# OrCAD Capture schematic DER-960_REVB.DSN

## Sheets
1 PAGE1: size Custom; title: HIPERPFS5 -220W Design
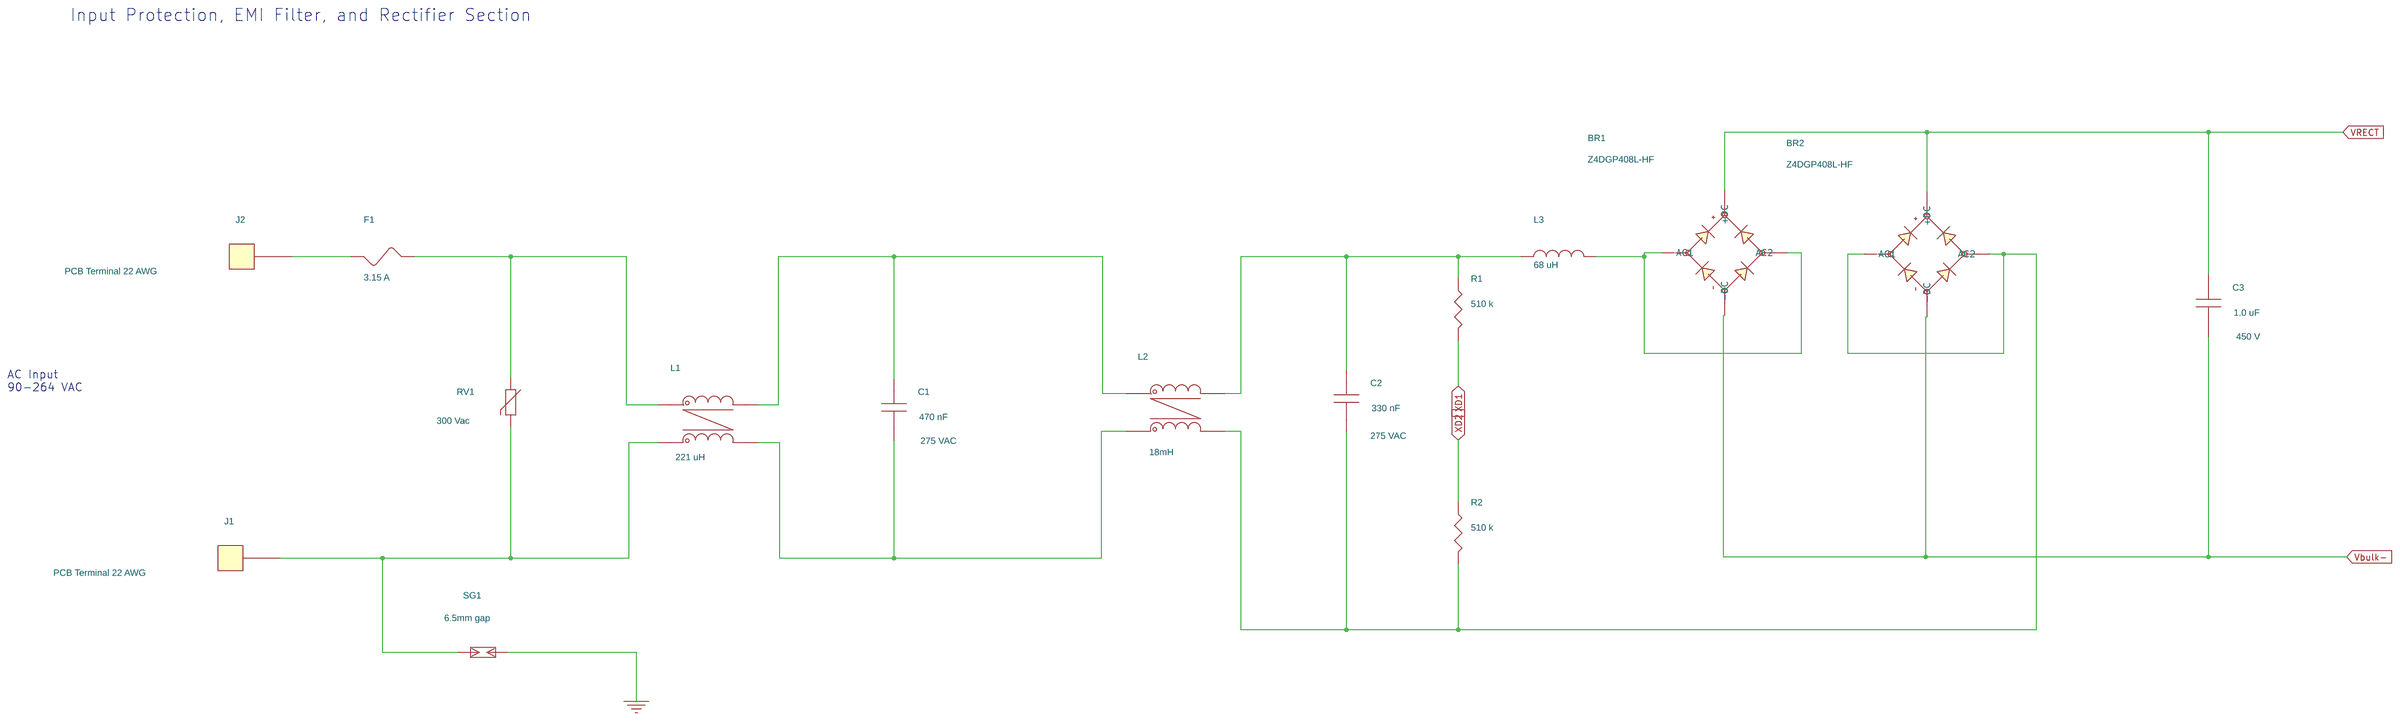
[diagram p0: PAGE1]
2 PAGE2: size C
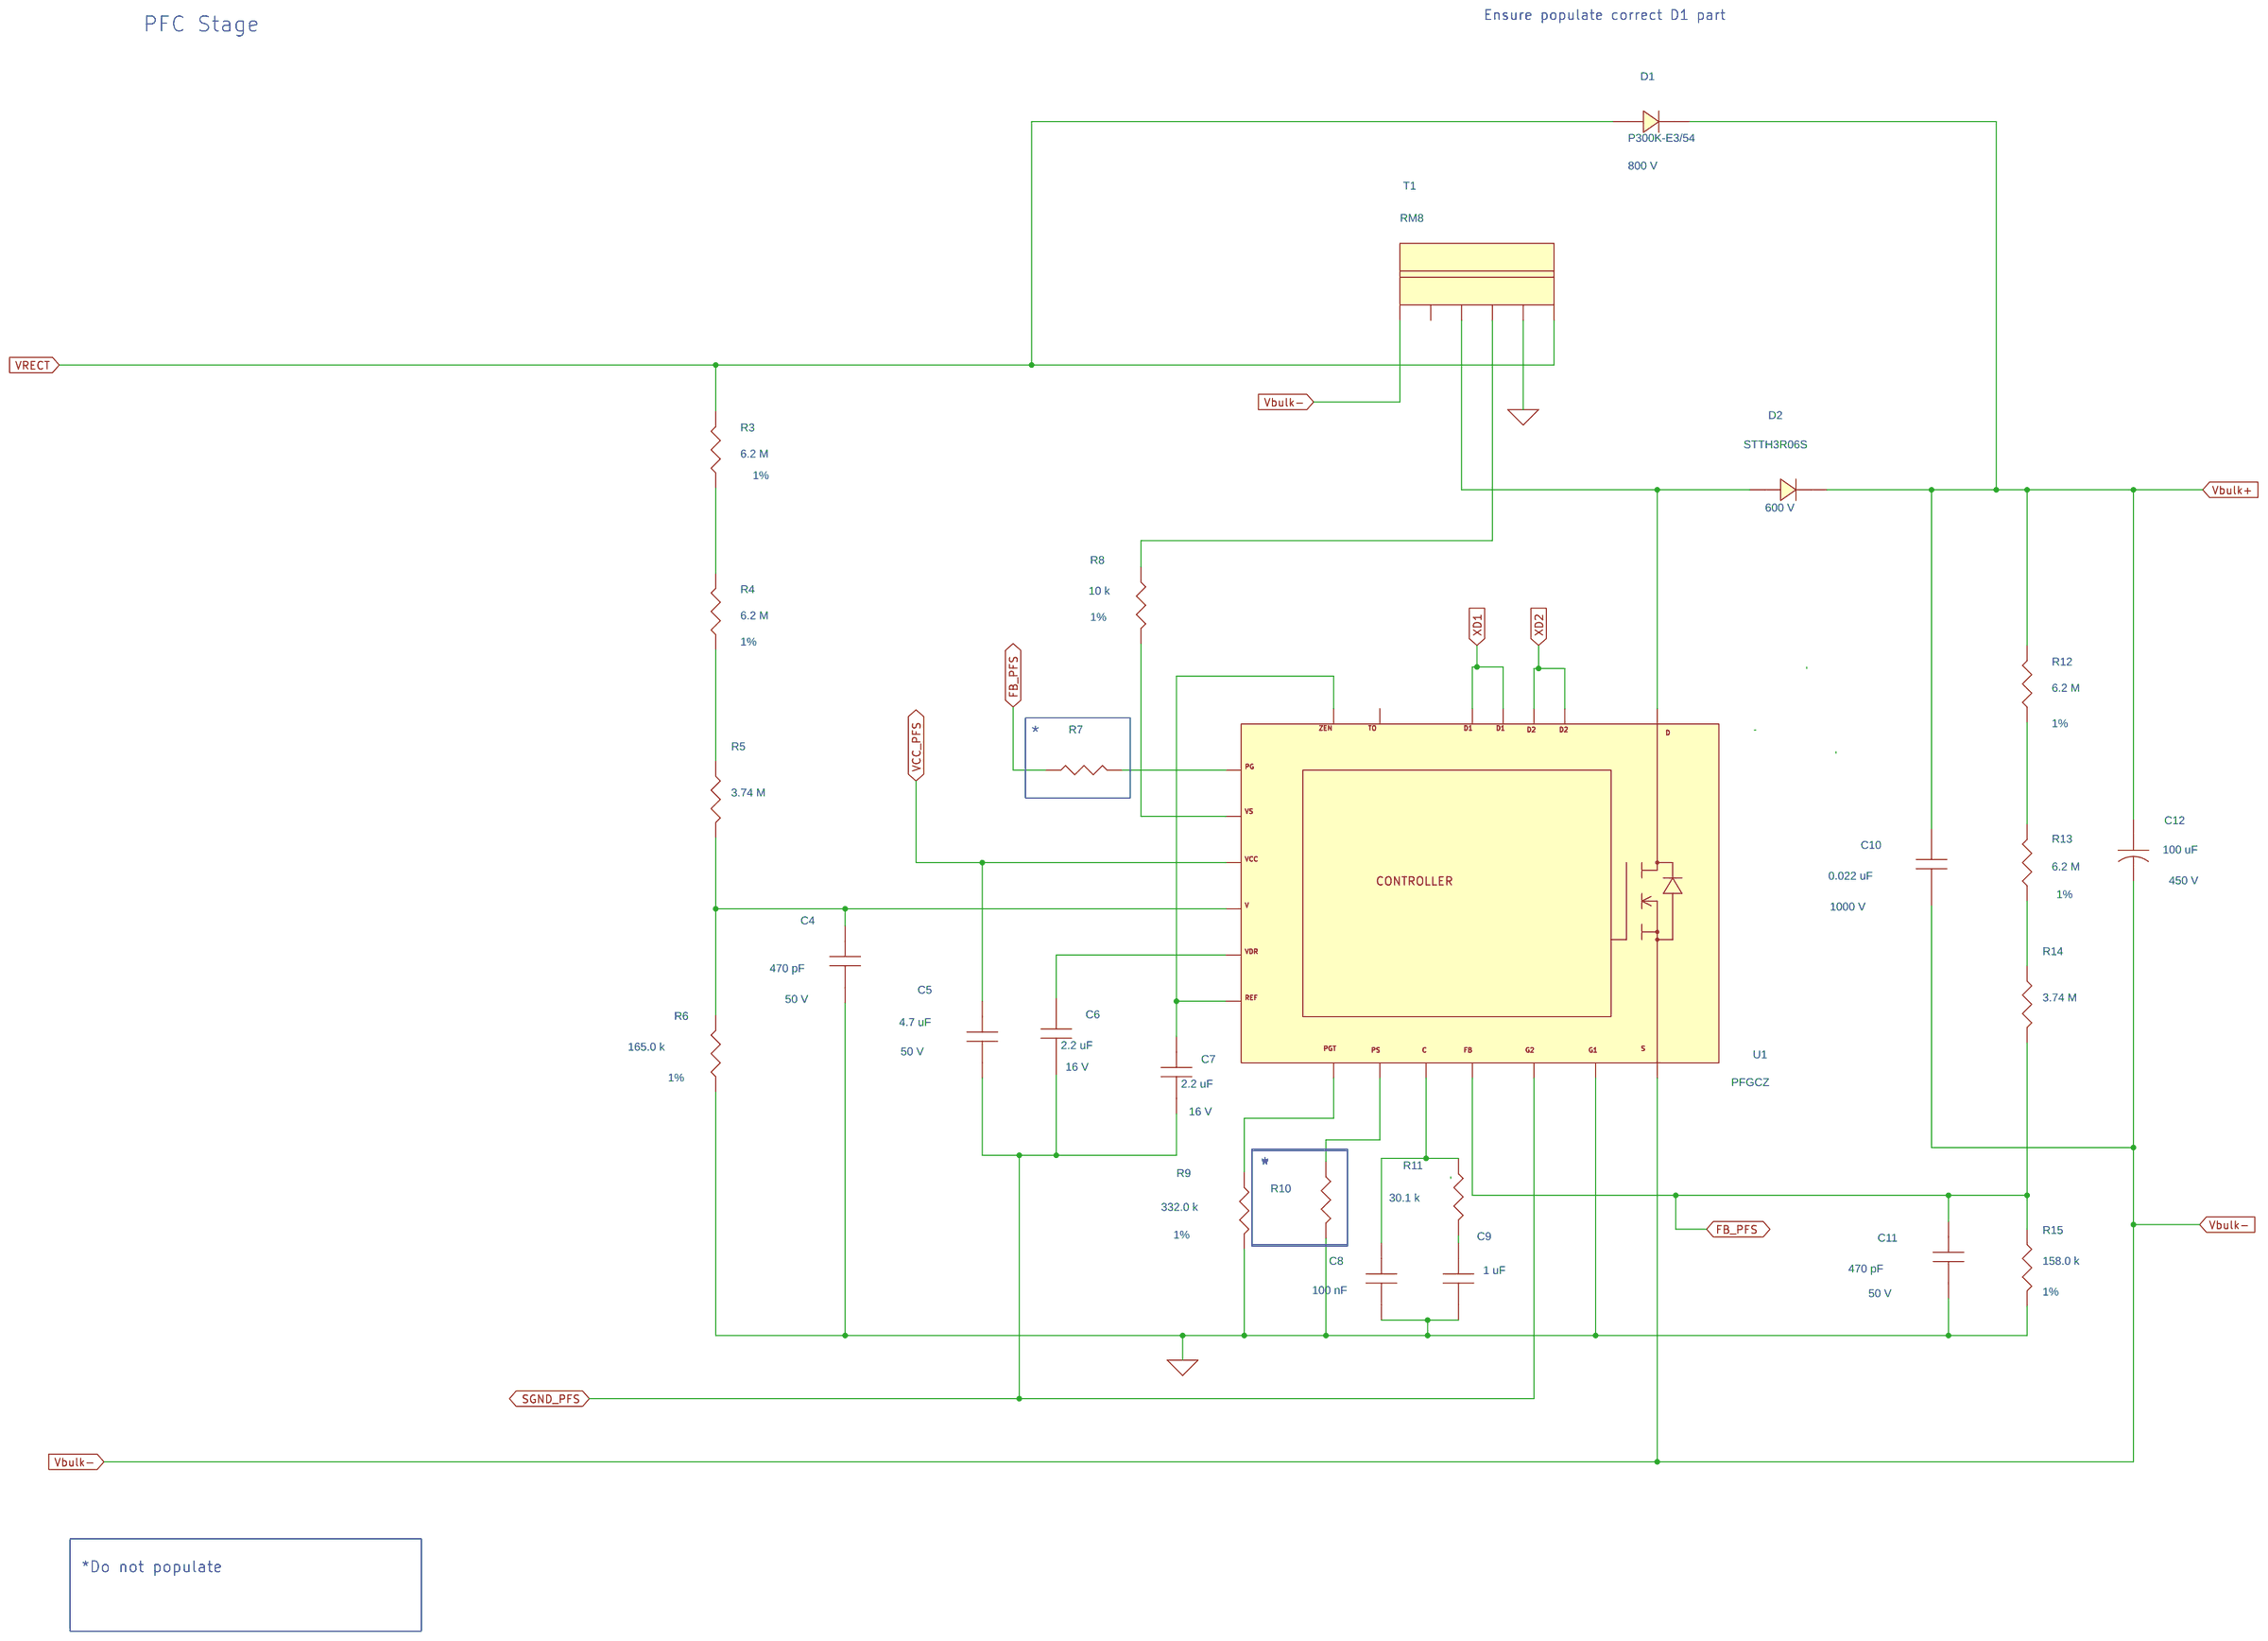
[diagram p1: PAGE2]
3 PAGE3: size C
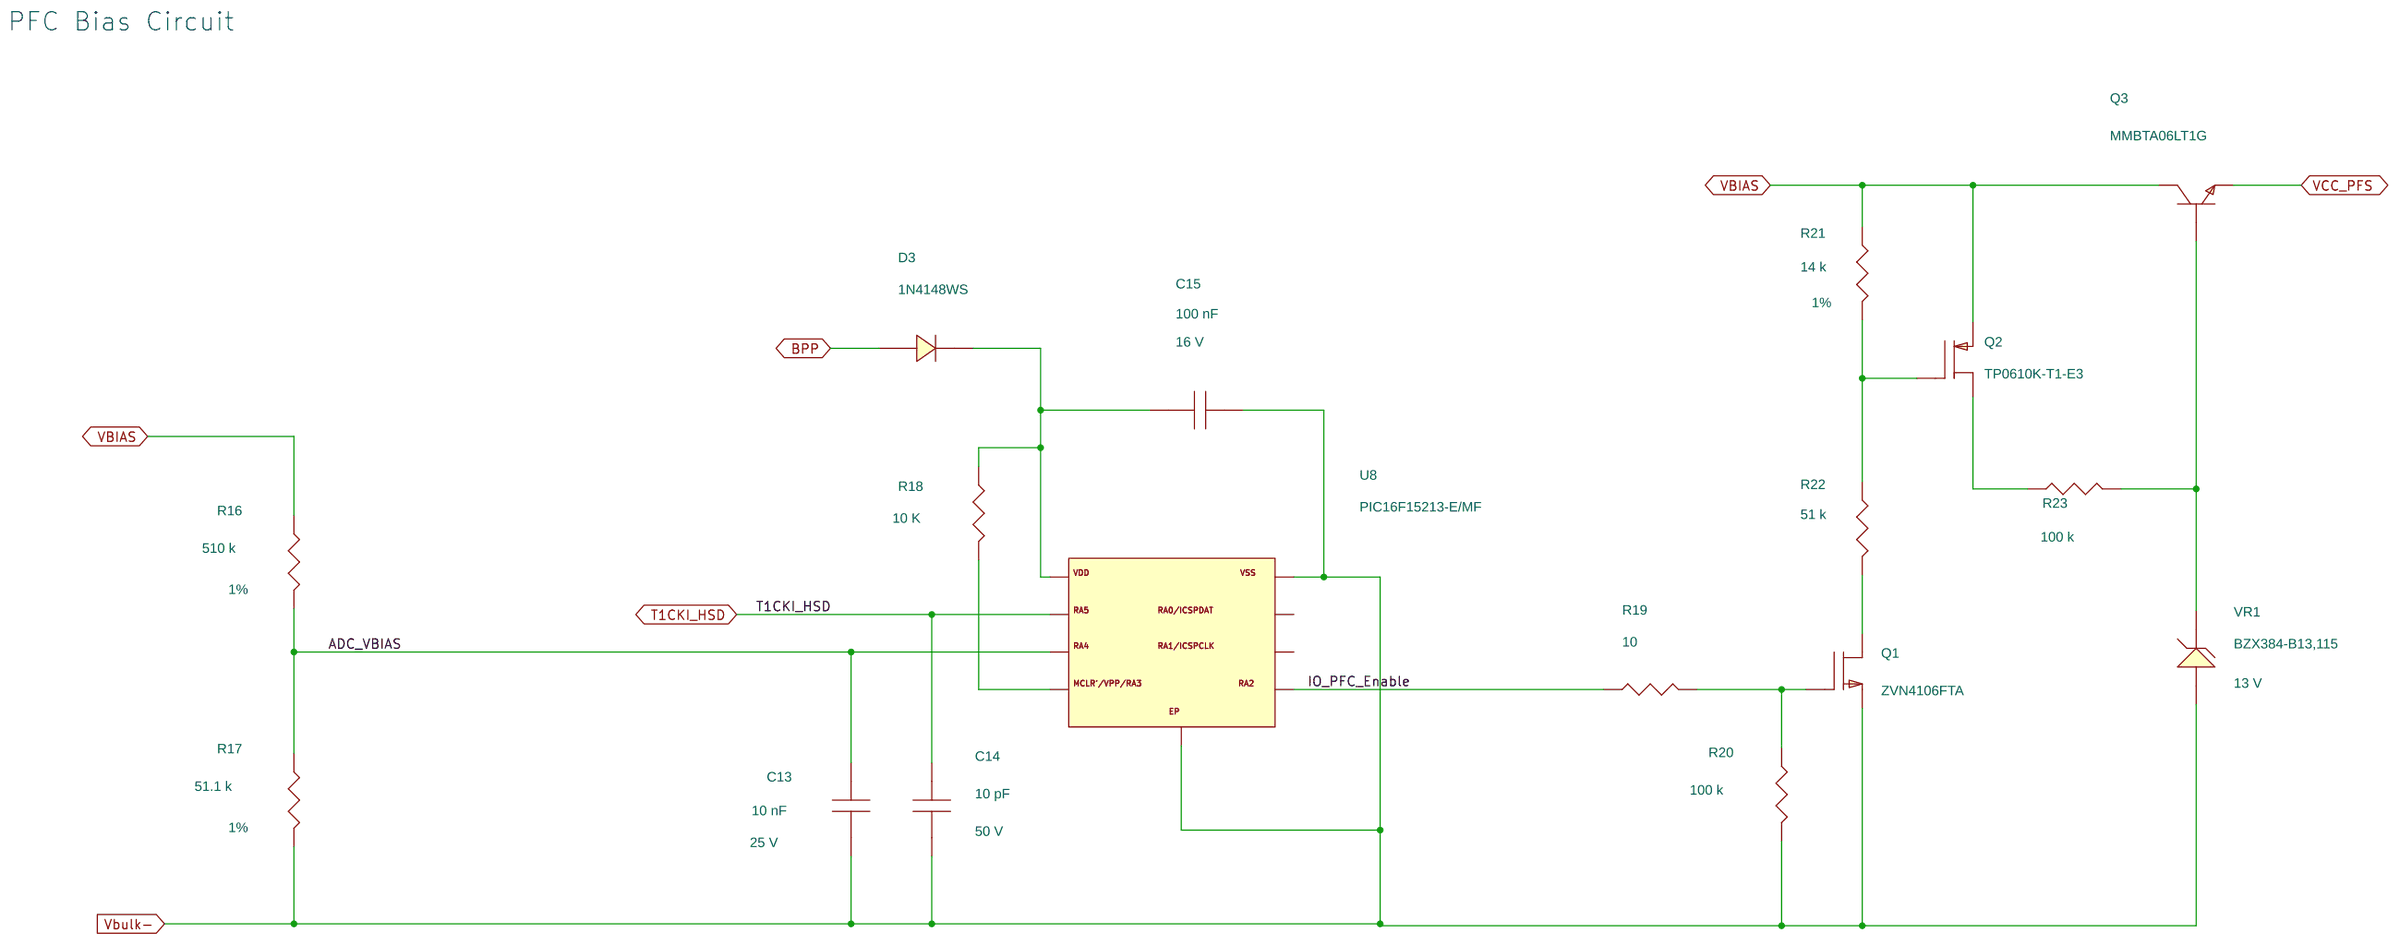
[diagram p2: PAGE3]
4 PAGE4: size Custom
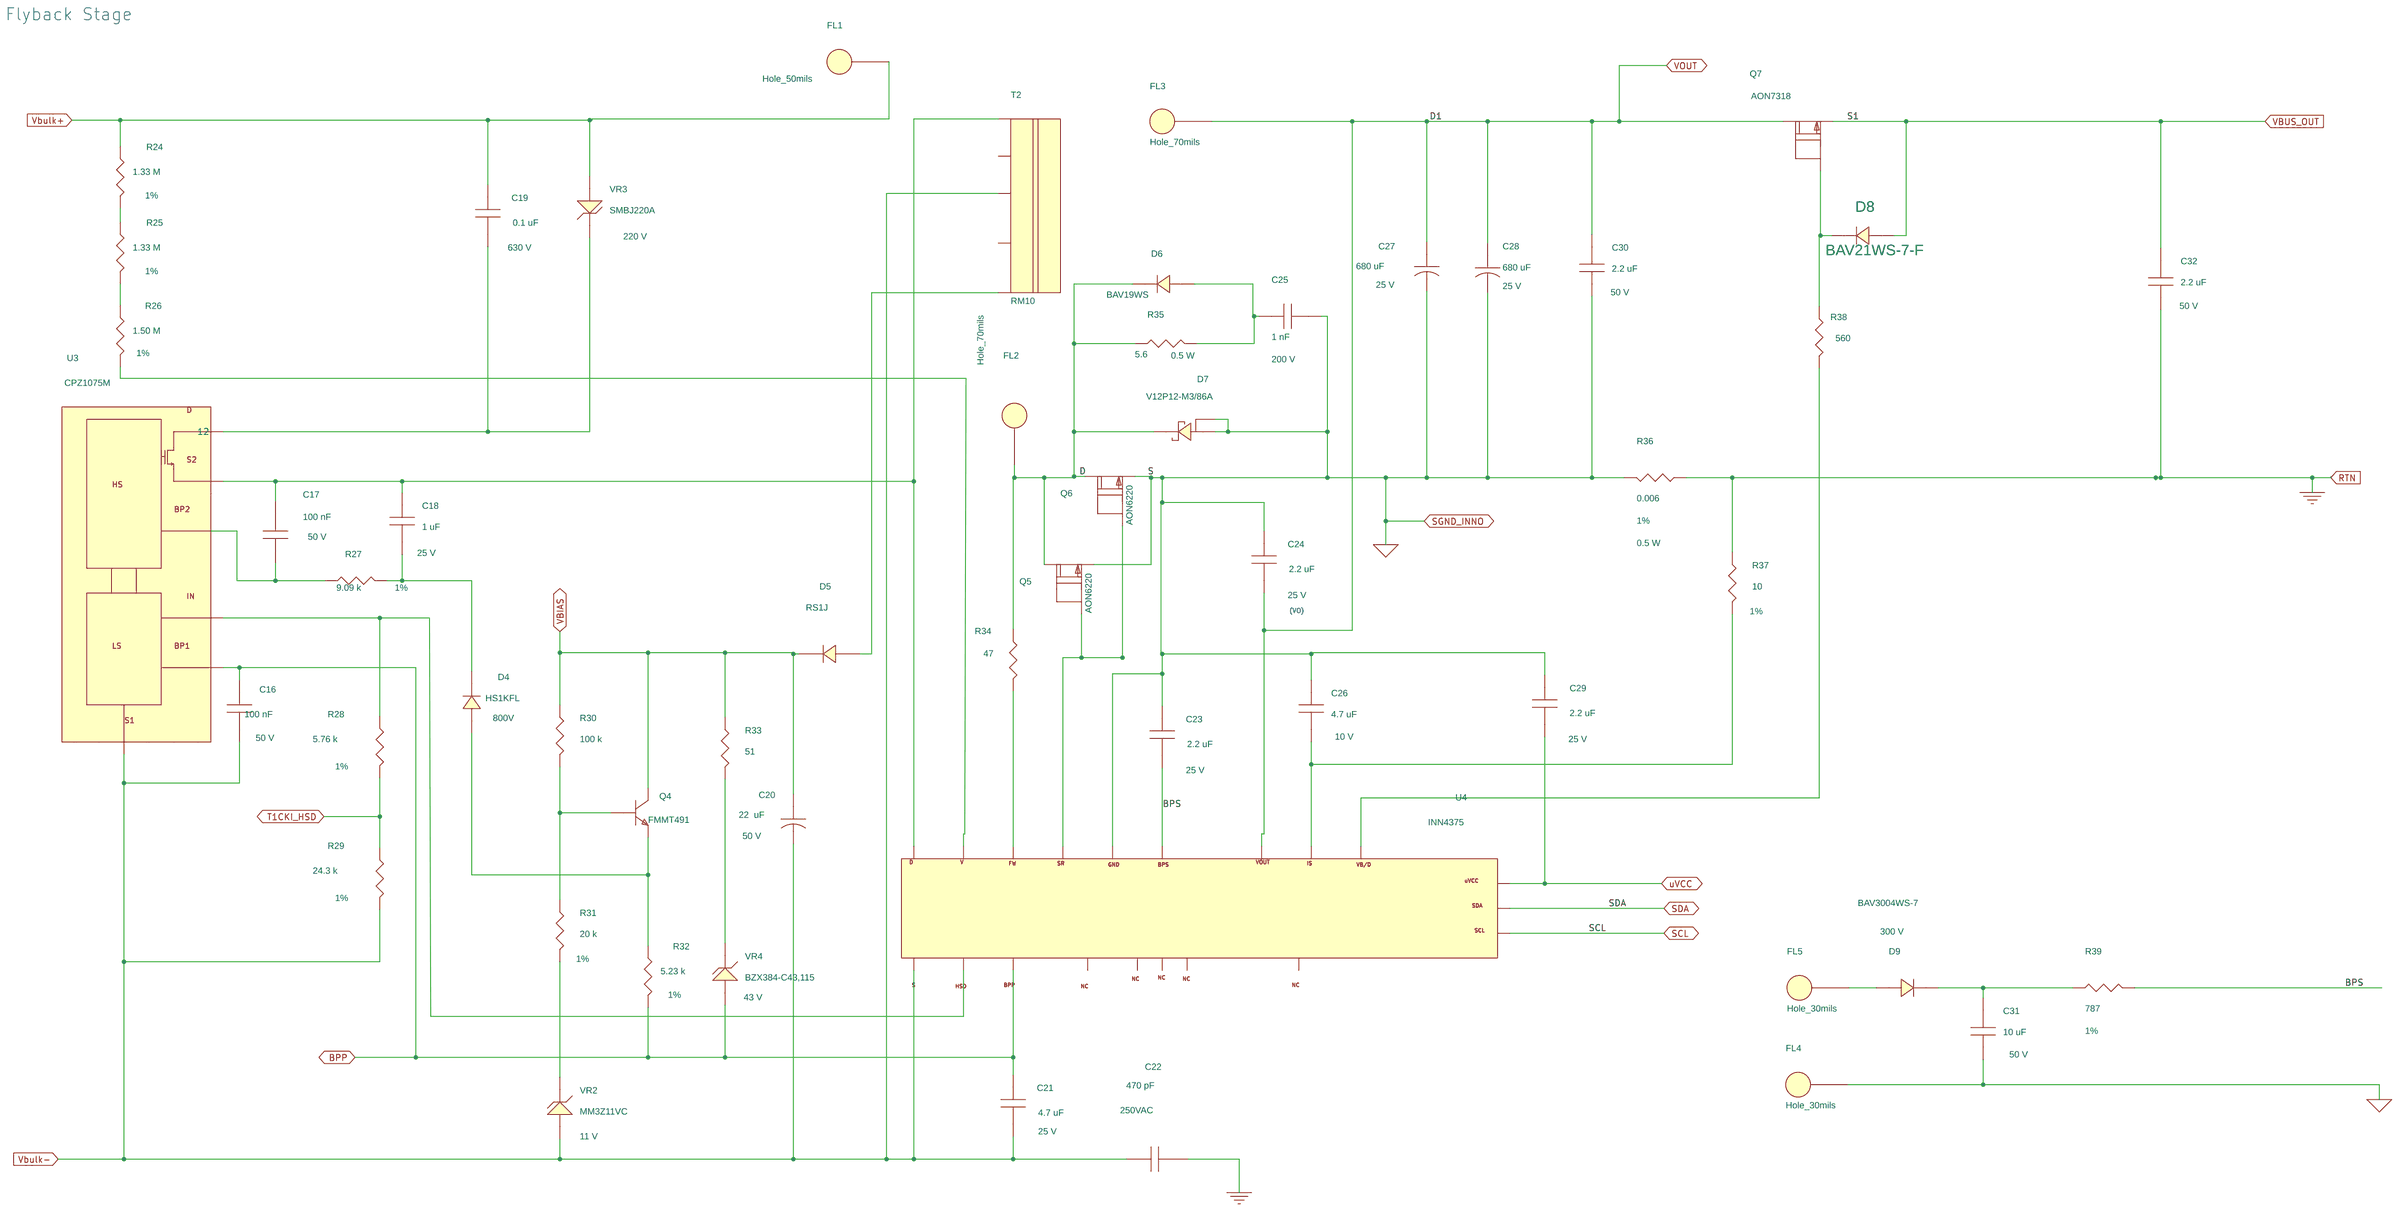
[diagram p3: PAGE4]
5 PAGE5: size C
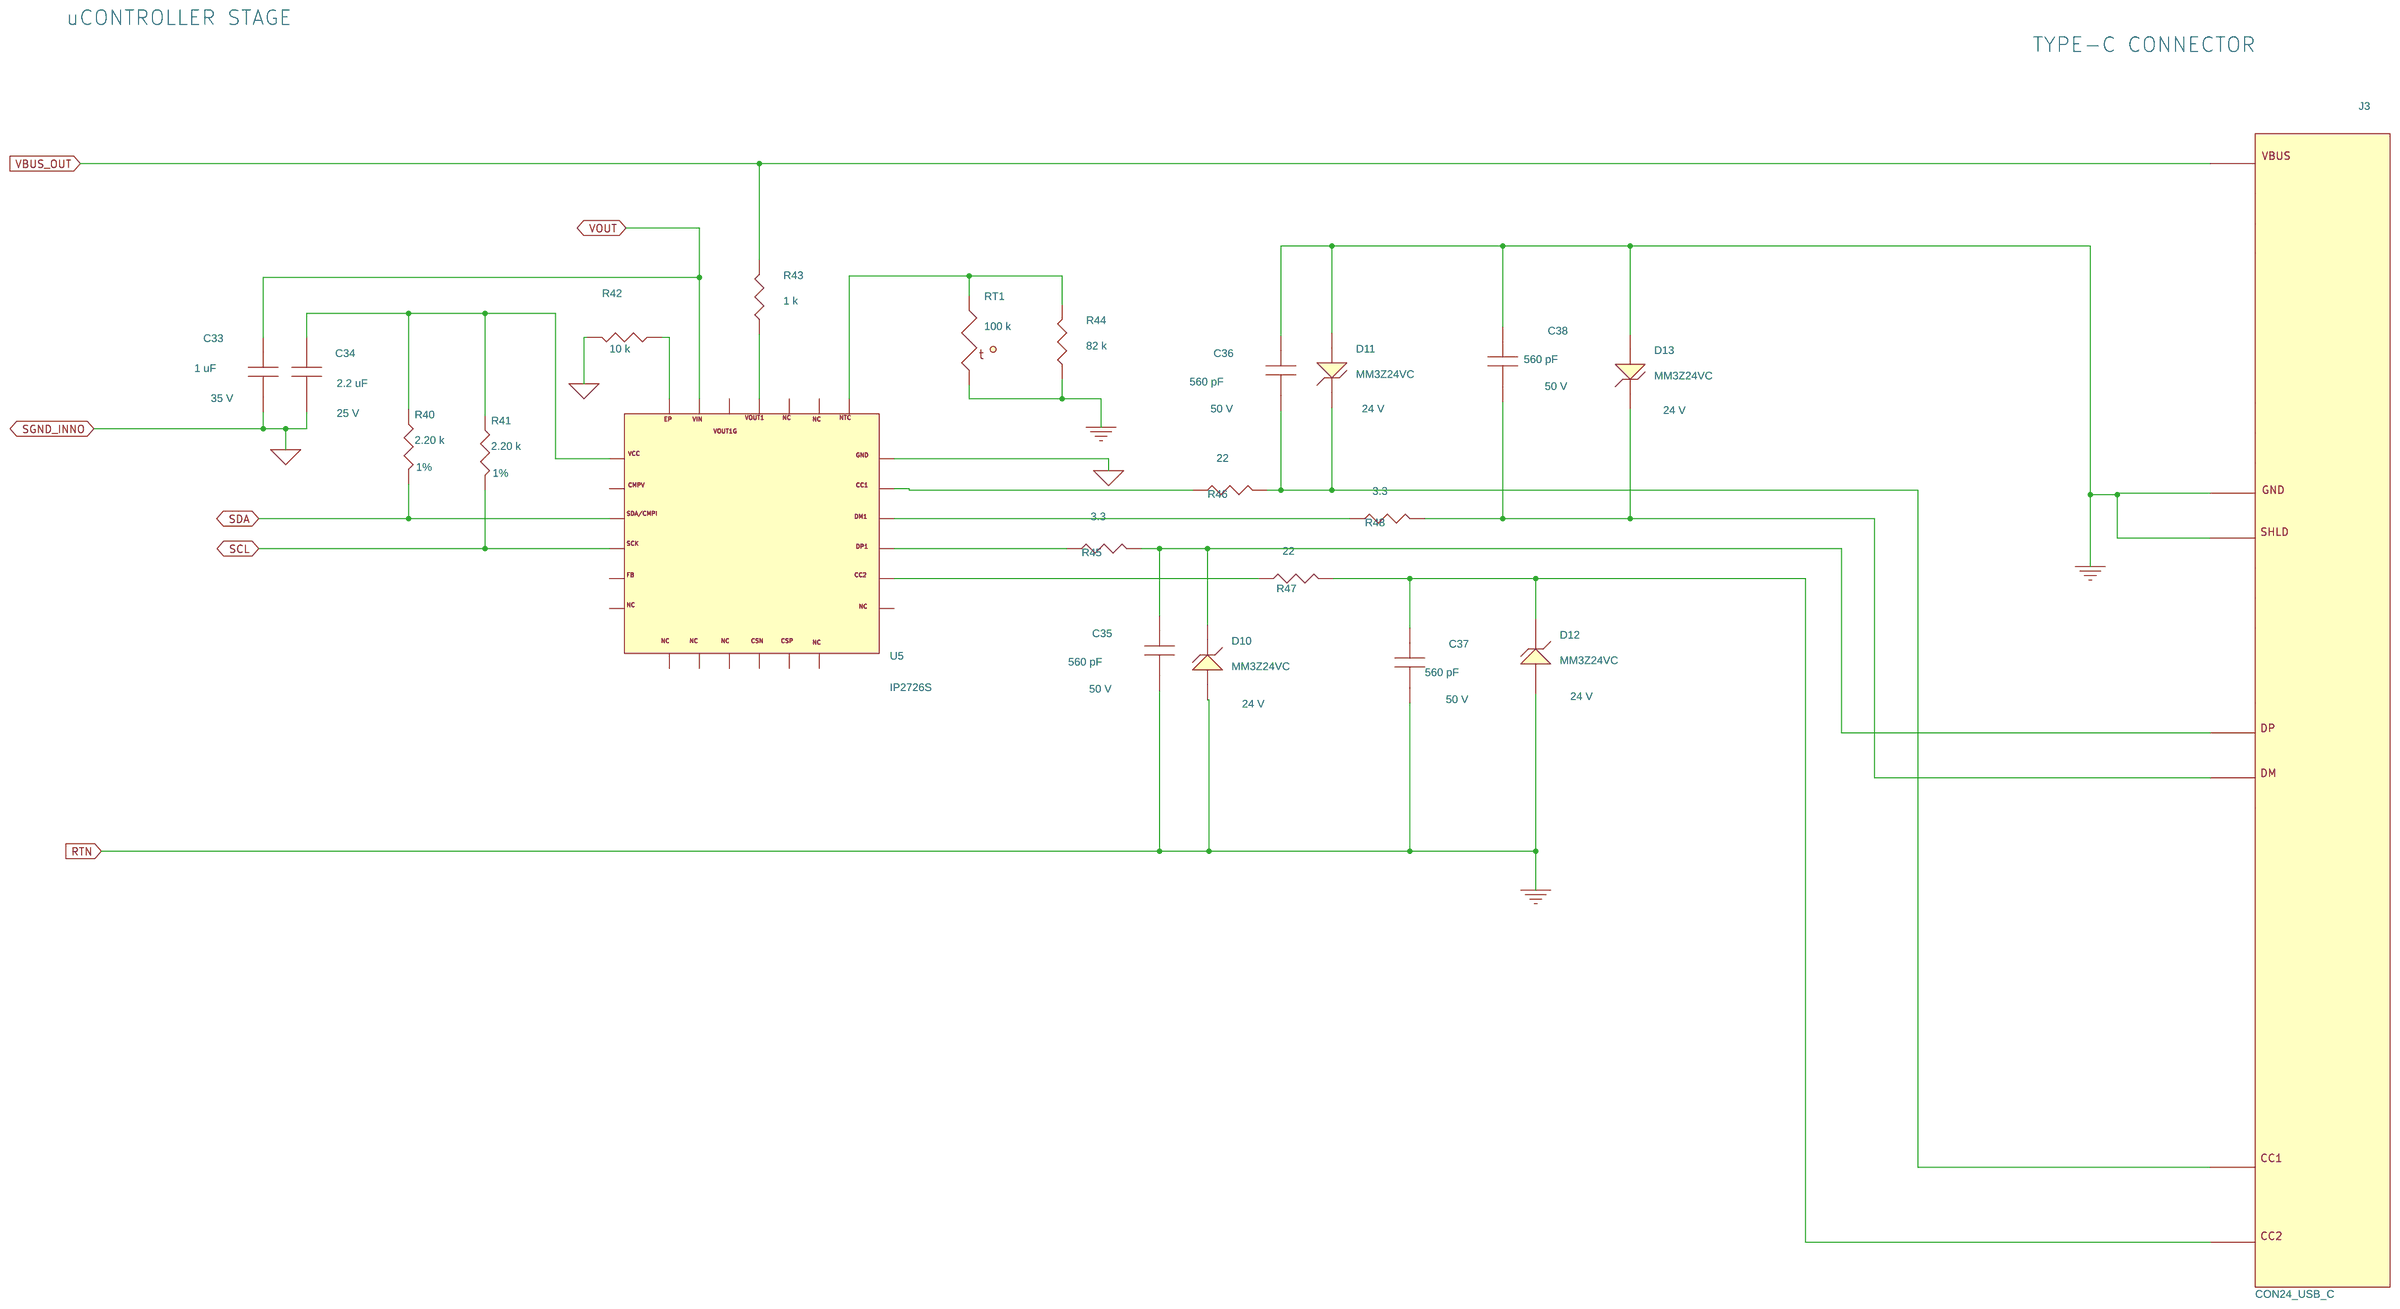
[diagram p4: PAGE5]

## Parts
sheet PAGE1
BR1  Z4DGP408L-HF  [pi_sm_d_z4d]
BR2  Z4DGP408L-HF  [pi_sm_d_z4d]
C1  470 nF  [pinpcaprad15x10mmd040]
C2  330 nF  [pinp_xcaprad15x8p5x14Hd040]
C3  1.0 uF  [pi_np_cap_rad717x335ls590d050]
F1  3.15 A  [pi_rst_microfuse]
J1  PCB Terminal 22 AWG  [pi_hole_22awg]
J2  PCB Terminal 22 AWG  [pi_hole_22awg]
L1  221 uH  [PI_4P_10XD4MMD40A]
L2  18mH  [pi_CMC_18mH_Sumida]
L3  68 uH  [pi2p14Dx6mmWd060]
R1  510 k  [pismr1206]
R2  510 k  [pismr1206]
RV1  300 Vac  [pidisc500x225ls335x140040]
SG1  6.5mm gap  [PI_SPARK_GAP_6p5MM]
sheet PAGE2
C4  470 pF  [pismr0402]
C5  4.7 uF  [pismc0805]
C6  2.2 uF  [pismc0402]
C7  2.2 uF  [pismc0402]
C8  100 nF  [pismr0402]
C9  1 uF  [pismr0402]
C10  0.022 uF  [pinpxcaprad5p5mmx4p0d040]
C11  470 pF  [pismr0402]
C12  100 uF  [pipolcapclyd18ls7p5mmd040]
D1  P300K-E3/54  [pidv300x200x060do15d0201ad]
D2  STTH3R06S  [pismdo214ab12]
R3  6.2 M  [pismr1206]
R4  6.2 M  [pismr1206]
R5  3.74 M  [pismr1206]
R6  165.0 k  [pismr0402]
R7  DNP  [pismr0603]
R8  10 k  [pismr0603]
R9  332.0 k  [pismr0402]
R10  DNP  [pismr0603]
R11  30.1 k  [pismr0402]
R12  6.2 M  [pismr1206]
R13  6.2 M  [pismr1206]
R14  3.74 M  [pismr1206]
R15  158.0 k  [pismr0402]
T1  RM8  [pi_bobbin_rm8_6p]
U1  PFGCZ  [inSOP-T28F]
sheet PAGE3
C13  10 nF  [pismc0603]
C14  10 pF  [pismc0603]
C15  100 nF  [pismr0402]
D3  1N4148WS  [pismdsod323]
Q1  ZVN4106FTA  [pismsot23123_1]
Q2  TP0610K-T1-E3  [pismsot23123_1]
Q3  MMBTA06LT1G  [pismsot23123_1]
R16  510 k  [pismr0603]
R17  51.1 k  [pismr0603]
R18  10 K  [pismr0402]
R19  10  [pismr0603]
R20  100 k  [pismr0603]
R21  14 k  [pismr0603]
R22  51 k  [pismr0603]
R23  100 k  [pismr0603]
U8  PIC16F15213-E/MF  [PI_SM_DFN83x3]
VR1  BZX384-B13,115  [pismsod323]
sheet PAGE4
C16  100 nF  [pismc0805]
C17  100 nF  [pismc0805]
C18  1 uF  [pismc0603]
C19  0.1 uF  [pismc1210]
C20  22  uF  [pipolcapclyd200ls80030]
C21  4.7 uF  [pismc0805]
C22  470 pF  [pinpcapraD7mmxLS10mm030]
C23  2.2 uF  [pismc0805]
C24  2.2 uF  [pismc0805]
C25  1 nF  [pismc0805]
C26  4.7 uF  [pismc0805]
C27  680 uF  [pipolcapcyld8mmd030]
C28  680 uF  [pipolcapcyld8mmd030]
C29  2.2 uF  [pismc0805]
C30  2.2 uF  [pismc0805]
C31  10 uF  [pismc1206]
C32  2.2 uF  [pismc0805]
D4  HS1KFL  [pi_sm_sod-123_12]
D5  RS1J  [pismdsma]
D6  BAV19WS  [pismsod323]
D7  V12P12-M3/86A  [pi_sm_d_to-277a]
D8  BAV21WS-7-F  [pismsod323]
D9  BAV3004WS-7  [pismsod323]
FL1  Hole_50mils  [pi_hole_50mil]
FL2  Hole_70mils  [pi_hole_70mil]
FL3  Hole_70mils  [pi_hole_70mil]
FL4  Hole_30mils  [pi_hole_30mil]
FL5  Hole_30mils  [pi_hole_30mil]
Q4  FMMT491  [pismsot23123_1]
Q5  AON6220  [pismpqfn5x6b]
Q6  AON6220  [pismpqfn5x6b]
Q7  AON7318  [pismdfn_ep3_3x3_3]
R24  1.33 M  [pismr1206]
R25  1.33 M  [pismr1206]
R26  1.50 M  [pismr1206]
R27  9.09 k  [pismr0805]
R28  5.76 k  [pismr0603]
R29  24.3 k  [pismr0603]
R30  100 k  [pismr0603]
R31  20 k  [pismr0603]
R32  5.23 k  [pismr0603]
R33  51  [pismr0603]
R34  47  [pismr0603]
R35  5.6  [pi12wvresd180ls150d040]
R36  0.006  [pismr0805]
R37  10  [pismr0603]
R38  560  [pismr0603]
R39  787  [pismr0603]
T2  RM10  [pi_bobbin_rm10_5p]
U3  CPZ1075M  [PI_SM_MinSOP16A_1]
U4  INN4375  [PI_IC_inSOP-T28D]
VR2  MM3Z11VC  [pismsod323]
VR3  SMBJ220A  [pismdo214aa12]
VR4  BZX384-C43,115  [pismsod323]
sheet PAGE5
C33  1 uF  [pismc0603]
C34  2.2 uF  [pismc0603]
C35  560 pF  [pismr0402]
C36  560 pF  [pismr0402]
C37  560 pF  [pismr0402]
C38  560 pF  [pismr0402]
D10  MM3Z24VC  [pismsod323F]
D11  MM3Z24VC  [pismsod323F]
D12  MM3Z24VC  [pismsod323F]
D13  MM3Z24VC  [pismsod323F]
J3  CON24_USB_C  [pi_conn_USBC_Wurth1]
R40  2.20 k  [pismr0402]
R41  2.20 k  [pismr0402]
R42  10 k  [pismr0402]
R43  1 k  [pismr0402]
R44  82 k  [pismr0603]
R45  3.3  [pismr0402]
R46  22  [pismr0402]
R47  22  [pismr0402]
R48  3.3  [pismr0402]
RT1  100 k  [pismr0603]
U5  IP2726S  [pi_sm_24_QFN]

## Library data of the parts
BR1 BR2 = DISCRETE_BRIDGE_+~~-: Part Number: 15-01113-00
C1 = CAP_NP: Disp_Voltage: 275 VAC; Part Number: 20-01413-00; Voltage: 275 VAC
C2 = CAP_NP: ALT_SYMBOLS: pinp_xcaprad15x8p5x14Hd040H; Disp_Voltage: 275 VAC; FPLIST: pinp_xcaprad15x8p5x14Hd040,pinp_xcaprad15x8p5x14Hd040H; Part Number: 20-09095-00; Voltage: 275 VAC
C3 = CAP_NP: ALT_SYMBOLS: pi_npcaprad717x335ls590d050H; Disp_Voltage: 450 V; FPLIST: pi_np_cap_rad717x335ls590d050,pi_npcaprad717x335ls590d050H; Part Number: 20-00925-00; Voltage: 450 V
F1 = FUSE: ALT_SYMBOLS: pirstmicrofusehoz; COMPGROUP: 1; FPLIST: pi_rst_microfuse,pirstmicrofusehoz; Part Number: 40-00020-00; ROOM: 1
J1 J2 = TERM_1Pin: Part Number: 35-00008-00; ROOM: 2
L1 = TORRID_4P_12_43a: ALT_SYMBOLS: pi_toroid_CMC4p_Ha,pi_toroid_CMC4p_V4123,pi_toroid_CMC4p_V_275uH; FPLIST: PI_4P_10XD4MMD40A,pi_toroid_CMC4p_Ha,pi_toroid_CMC4p_V4123,pi_toroid_CMC4p_V_275uH; Part Number: 32-00431-00
L2 = TORRID_4P_12_43a: ALT_SYMBOLS: pi_CMC_18mH_SumidaW,pi_CMC_18mH_Sumida_H; FPLIST: pi_CMC_18mH_Sumida,pi_CMC_18mH_SumidaW,pi_CMC_18mH_Sumida_H; Part Number: 30-00462-00
L3 = INDUCTOR: Part Number: 32-00411-00
R1 R2 = R: Part Number: 05-01417-00; ROOM: 1
RV1 = VARISTOR: Part Number: 85-00026-00
SG1 = SPARK_GAP: Part Number: 66-00355-00
C4 C11 = CAP_NP: ALT_SYMBOLS: pismr0402_1; Disp_Voltage: 50 V; FPLIST: pismr0402,pismr0402_1; Part Number: 20-09060-00; ROOM: 2; Voltage: 50 V
C5 = CAP_NP: Disp_Voltage: 50 V; Part Number: 20-01130-00; ROOM: 2; Voltage: 50 V
C6 C7 = CAP_NP: ALT_SYMBOLS: pismr0402_1; Disp_Voltage: 16 V; FPLIST: pismc0402,pismr0402_1; Part Number: 20-09202-00; ROOM: 2; Voltage: 16 V
C8 = CAP_NP: ALT_SYMBOLS: pismr0402_1; Disp_Voltage: 16 V; FPLIST: pismr0402,pismr0402_1; Part Number: 20-08759-00; ROOM: 2; Voltage: 16 V
C9 = CAP_NP: ALT_SYMBOLS: pismr0402_1; Disp_Voltage: 25 V; FPLIST: pismr0402,pismr0402_1; Part Number: 20-09151-00; ROOM: 2; Voltage: 25 V
C10 = CAP_NP: Disp_Voltage: 1000 V; Part Number: 20-09167-00; Voltage: 1000 V
C12 = CAP_POL: ALT_SYMBOLS: pipolcapclyd18ls7p5h25mmd040; Disp_Voltage: 450 V; FPLIST: pipolcapclyd18ls7p5mmd040,pipolcapclyd18ls7p5h25mmd040; Part Number: 20-01593-00; Voltage: 450 V
D1 = DIODE: ALT_SYMBOLS: pidax800x225060do15do201ad,pidv300x200x060do14wbead; Disp_Voltage: 800 V; FPLIST: pidv300x200x060do15d0201ad,pidax800x225060do15do201ad,pidv300x200x060do14wbead; Part Number: 15-01773-00
D2 = DIODE: Disp_Voltage: 600 V; Part Number: 15-00827-00
R3 R4 R12 R13 = R: Disp_Tol: 1%; Part Number: 05-05567-00; ROOM: 2
R5 R14 = R: Part Number: 05-05572-00; ROOM: 2
R6 = R: Disp_Tol: 1%; Part Number: 05-06059-00; ROOM: 2
R7 = R: Part Number: 05-01747-00
R8 = R: Disp_Tol: 1%; Part Number: 05-03182-00; ROOM: 2
R9 = R: Disp_Tol: 1%; Part Number: 05-06091-00; ROOM: 2
R10 = R: Disp_Tol: 1%; Part Number: 05-06522-00; ROOM: 2
R11 = R: Disp_Tol: 1%; Part Number: 05-05984-00; ROOM: 2
R15 = R: Disp_Tol: 1%; Part Number: 05-06056-00; ROOM: 2
T1 = BRM8_6P_6-0: Part Number: 25-01147-00; ROOM: 2
U1 = PFSGaN_InSOP-T28F28: Part Number: 10-01271-00; ROOM: 2
C13 = CAP_NP: Disp_Voltage: 25 V; Part Number: 20-09120-00; Voltage: 25 V
C14 = CAP_NP: Disp_Voltage: 50 V; Part Number: 20-09099-00; ROOM: 2; Voltage: 50 V
C15 = CAP_NP: ALT_SYMBOLS: pismr0402_1; Disp_Voltage: 16 V; FPLIST: pismr0402,pismr0402_1; Part Number: 20-08759-00; Voltage: 16 V
D3 = DIODE: Part Number: 15-01163-00; ROOM: 3
Q1 = FET_N_GSD: Part Number: 50-00361-00
Q2 = FET_P_GSD_1: Part Number: 50-00093-00; ROOM: 3
Q3 = NPN_BEC: Part Number: 55-00072-00; ROOM: 3
R16 = R: Disp_Tol: 1%; Part Number: 05-03474-00
R17 = R: Disp_Tol: 1%; Part Number: 05-03252-00
R18 = R: Part Number: 05-03488-00
R19 = R: Part Number: 05-01640-00
R20 R30 = R: Part Number: 05-01736-00
R21 = R: Disp_Tol: 1%; Part Number: 05-03196-00; ROOM: 3
R22 = R: Part Number: 05-01729-00; ROOM: 3
R23 = R: Part Number: 05-01736-00; ROOM: 3
U8 = PIC16F15213-E_MF: Part Number: 45-04544-00
VR1 = DIODE_ZENER: Disp_Voltage: 13 V; Part Number: 15-00819-00; ROOM: 3
C16 C17 = CAP_NP: Disp_Voltage: 50 V; Part Number: 20-00904-00; ROOM: 5; Voltage: 50 V
C18 = CAP_NP: ALT_SYMBOLS: pismc0603_1; Disp_Voltage: 25 V; FPLIST: pismc0603,pismc0603_1; Part Number: 20-09147-00; Voltage: 25 V
C19 = CAP_NP: Disp_Voltage: 630 V; Part Number: 20-01588-00; Voltage: 630 V
C20 = CAP_POL: ALT_SYMBOLS: pipolcapclyd200ls80030h; Disp_Voltage: 50 V; FPLIST: pipolcapclyd200ls80030,pipolcapclyd200ls80030h; Part Number: 20-00950-00; ROOM: 5; Voltage: 50 V
C21 = CAP_NP: Disp_Voltage: 25 V; Part Number: 20-09022-00; Voltage: 25 V
C22 = CAP_NP: Disp_Voltage: 250VAC; Part Number: 20-01454-00; ROOM: 2; Voltage: 250VAC
C23 C24 C29 = CAP_NP: Disp_Voltage: 25 V; Part Number: 20-09264-00; Voltage: 25 V
C25 = CAP_NP: ALT_SYMBOLS: pismc0805_1; Disp_Voltage: 200 V; FPLIST: pismc0805,pismc0805_1; Part Number: 20-00737-00; Voltage: 200 V
C26 = CAP_NP: Disp_Voltage: 10 V; Part Number: 20-00612-00; Voltage: 10 V
C27 C28 = CAP_POL: ALT_SYMBOLS: pipolcapcyld8x16mmd030H; Disp_Voltage: 25 V; FPLIST: pipolcapcyld8mmd030,pipolcapcyld8x16mmd030H; Part Number: 20-01579-00; ROOM: 4; Voltage: 25 V
C30 C32 = CAP_NP: Disp_Voltage: 50 V; Part Number: 20-09011-00; Voltage: 50 V
C31 = CAP_NP: ALT_SYMBOLS: pismc1206_1; Disp_Voltage: 50 V; FPLIST: pismc1206,pismc1206_1; Part Number: 20-08995-00; ROOM: 3; Voltage: 50 V
D4 = DIODE: Disp_Voltage: 800V; Part Number: 15-01686-00
D5 = DIODE: COMPGROUP: 1; Part Number: 15-00432-00; ROOM: 5
D6 = DIODE: Part Number: 15-00658-00
D7 = DIODE_SCHOTTKY_TO-277A: Part Number: 15-01194-00
D8 = DIODE: COMPGROUP: 1; Part Number: 15-00385-00; ROOM: 3
D9 = DIODE: COMPGROUP: 1; Disp_Voltage: 300 V; Part Number: 15-01138-00; ROOM: 3
FL1 = FlyingLead: Part Number: 35-00283-00; ROOM: 4
FL2 FL3 = FlyingLead: Part Number: 35-00282-00; ROOM: 4
FL4 FL5 = FlyingLead: Part Number: 35-00284-00
Q4 = NPN_BEC: Part Number: 55-00035-00
Q5 Q6 = FET_N_SGD_123_4_5678: Part Number: 50-00276-00; ROOM: 4
Q7 = FET_N_SGD_123_4_5678: Part Number: 50-00331-00
R24 R25 = R: Disp_Tol: 1%; Part Number: 05-05444-00
R26 = R: Disp_Tol: 1%; Part Number: 05-03153-00
R27 = R: Disp_Tol: 1%; Part Number: 05-03397-00
R28 = R: Disp_Tol: 1%; Part Number: 05-01151-00
R29 = R: Disp_Tol: 1%; Part Number: 05-03221-00
R31 = R: Disp_Tol: 1%; Part Number: 05-03213-00
R32 = R: Disp_Tol: 1%; Part Number: 05-01147-00
R33 = R: Part Number: 05-01657-00
R34 = R: ALT_SYMBOLS: pismr0603_1; FPLIST: pismr0603,pismr0603_1; Part Number: 05-01656-00; ROOM: 4
R35 = R: ALT_SYMBOLS: pi12wvresd180ls200d040,pi12wvresd180ls250d040,pi12wresd180ls675d040; Disp_Power: 0.5 W; FPLIST: pi12wvresd180ls150d040,pi12wvresd180ls200d040,pi12wvresd180ls250d040,pi12wresd180ls675d040; Part Number: 05-02621-00
R36 = R: Disp_Power: 0.5 W; Disp_Tol: 1%; Part Number: 05-06516-00
R37 = R: Disp_Tol: 1%; Part Number: 05-00886-00
R38 = R: Part Number: 05-01682-00; ROOM: 3
R39 = R: Disp_Tol: 1%; Part Number: 05-01068-00
T2 = BRM10_5P_GENERIC: ALT_SYMBOLS: pi_bobbin_rm10_5p_clp; FPLIST: pi_bobbin_rm10_5p,pi_bobbin_rm10_5p_clp; Part Number: 25-00921-00
U3 = ClampZeroMinSOP16: Part Number: 10-01330-00
U4 = DEV_INN4375: Part Number: 10-01269-00
VR2 = DIODE_ZENER: Disp_Voltage: 11 V; Part Number: 15-01658-00
VR3 = DIODE_ZENER: Disp_Voltage: 220 V; Part Number: 15-01317-00
VR4 = DIODE_ZENER: Disp_Voltage: 43 V; Part Number: 15-01599-00
C33 = CAP_NP: ALT_SYMBOLS: pismc0603_1; Disp_Voltage: 35 V; FPLIST: pismc0603,pismc0603_1; Part Number: 20-09226-00; ROOM: 4; Voltage: 35 V
C34 = CAP_NP: ALT_SYMBOLS: pismc0603_1; Disp_Voltage: 25 V; FPLIST: pismc0603,pismc0603_1; Part Number: 20-09023-00; ROOM: 4; Voltage: 25 V
C35-C38 = CAP_NP: ALT_SYMBOLS: pismr0402_1,cc0402; Disp_Voltage: 50 V; FPLIST: pismr0402,pismr0402_1,cc0402; Part Number: 20-01586-00; ROOM: 6; Voltage: 50 V
D10-D13 = DIODE_ZENER: Disp_Voltage: 24 V; Part Number: 15-01590-00; ROOM: 6
J3 = CON24_USBgjc1_0: FPLIST: pi_conn_USBC_Wurth,pi_conn_USBC_Wurth1; Part Number: 35-00414-00; ROOM: 6
R40 R41 = R: ALT_SYMBOLS: RC0402; Disp_Tol: 1%; FPLIST: pismr0402,RC0402; Part Number: 05-05859-00
R42 = R: COMPGROUP: 1; Part Number: 05-06235-00; ROOM: 6
R43 = R: ALT_SYMBOLS: pismr0402_1; COMPGROUP: 1; FPLIST: pismr0402,pismr0402_1; Part Number: 05-03420-00; ROOM: 6
R44 = R: Part Number: 05-01734-00; ROOM: 4
R45 R48 = R: COMPGROUP: 1; Part Number: 05-06160-00; ROOM: 6
R46 R47 = R: COMPGROUP: 1; Part Number: 05-06177-00; ROOM: 6
RT1 = THERMISTOR: Part Number: 90-00078-00; ROOM: 6
U5 = IP2726S: Part Number: 45-00668-99

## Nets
GND: C22.2 C32.1 C35.2 C36.1 C37.2 C38.1 D10.2 D11.2 D12.2 D13.2 J3.A1 J3.S1 R36.1 R37.1 R44.1 RT1.2 SG1.2
GND_SIGNAL: C4.2 C8.2 C9.2 C11.2 C23.1 C24.1 C25.2 C26.1 C27.2 C28.2 C29.1 C30.1 C31.1 C33.2 C34.2 D7.1(A1) D7.2(A2) FL4.1 Q5.1(S) Q6.1(S) R6.2 R9.2 R10.2 R15.2 R36.2 R42.1 T1.5 U1.2 U4.2 U5.18
SGND_PFS: C5.2 C6.2 C7.2 U1.13
VBUS_OUT: C32.2 D8.2 J3.A4 Q7.1(S) R43.1
VCC_PFS: C5.1 Q3.2(EMITTER) U1.14
ADC_VBIAS: C13.1 R16.2 R17.1 U8.3
BPP: C16.1 C21.1 D3.2 R32.2 U3.8 U4.17 VR4.2
BPS: C23.2 R39.2 U4.4
D: D6.1 D7.3(Cathode) FL2.1 Q5.5(D) Q6.5(D) R34.1 R35.1
FB_PFS: C11.1 R7.1 R14.2 R15.1 U1.6
IO_PFC_Enable: R19.1 U8.5
SCL: R41.2 U4.5 U5.4
SDA: R40.2 U4.6 U5.3
T1CKI_HSD: C14.1 R28.2 R29.1 U8.2
uVCC: C29.2 U4.7
VBIAS: C20.1 D5.1 Q2.2(S) Q3.3(COLLECTOR) Q4.3(COLLECTOR) R16.1 R21.1 R30.1 R33.1
Vbulk+: C10.1 C12.1 C19.1 D1.1 D2.1 FL1.1 R12.2 R24.1 VR3.2
Vbulk-: BR1.4(-DC) BR2.4(-DC) C3.2 C10.2 C12.2 C13.2 C14.2 C15.1 C16.2 C20.2 C21.2 C22.1 Q1.2(S) R17.2 R20.2 R29.2 T1.1 T2.3 U1.21 U3.3 U4.19 U8.8 U8.9 VR1.2 VR2.2
VOUT: C24.2 C27.1 C28.1 C30.2 C33.1 FL3.1 Q7.5(D) U4.10 U5.24
VRECT: BR1.1(+DC) BR2.1(+DC) C3.1 D1.2 R3.2 T1.6
XD1: R1.2 U1.15 U1.16
XD2: R2.1 U1.18 U1.19
N12562444: F1.2 J2.1
N12978385: C36.2 D11.1 J3.A5 R46.1
N12978393: C38.2 D13.1 J3.A7 R48.1
N12978617: C35.1 D10.1 J3.A6 R45.1
N12978703: C37.1 D12.1 J3.B5 R47.1
N12982078: C17.2 C18.1 T2.1 U3.10 U4.28
N12982116: D8.1 Q7.4(G) R38.2
N12982138: C19.2 U3.16(12) VR3.1
N12982146: D5.2 T2.5
N12982194: R24.2 R25.1
N12982278: C25.1 D6.2 R35.2
N12982430: R26.2 U4.15
N12982780: C17.1 R27.1 U3.9
N12982804: C18.2 D4.1 R27.2
N12983124: R28.1 U3.7 U4.18
N12983212: D4.2 Q4.2(EMITTER) R32.1
N12983344: R34.2 U4.11
N12983580: C26.2 R37.2 U4.1
N12983610: Q4.1(BASE) R30.2 R31.1
N12983664: R33.2 VR4.1
N12983698: R38.1 U4.8
N12983998: R31.2 VR2.1
N12984120: D9.2 FL5.1
N12984124: C31.2 D9.1 R39.1
N13017871: Q5.4(G) Q6.4(G) U4.9
N13110214: R44.2 RT1.1 U5.19
N13117437: C34.1 R40.1 R41.1 U5.1
N13120477: R46.2 U5.17
N13120713: R48.2 U5.16
N13120918: R45.2 U5.15
N13120931: R47.2 U5.14
N13202099: R43.2 U5.22
N13202419: R42.2 U5.25
N13240154: J1.1 L1.1 RV1.2 SG1.1
N13240664: F1.1 L1.4 RV1.1
N13240668: C1.1 L1.3 L2.4
N13240680: C2.1 L2.3 L3.1 R1.1
N13240864: C1.2 L1.2 L2.1
N13240868: BR2.2(AC1) BR2.3(AC2) C2.2 L2.2 R2.2
N13242621: D2.2 T1.3 U1.28
N13242625: R8.1 T1.4
N13242683: R3.1 R4.2
N13242925: R8.2 U1.1
N13242929: R12.1 R13.2
N13243031: C4.1 R5.2 R6.1 U1.4
N13243105: R13.1 R14.1
N13243177: C6.1 U1.12
N13243227: C7.1 U1.10 U1.11
N13243301: R9.1 U1.8
N13243305: R10.1 U1.9
N13243309: C8.1 R11.1 U1.5
N13243495: C9.1 R11.2
N13249102: BR1.2(AC1) BR1.3(AC2) L3.2
N13253978: R7.2 U1.7
N13264968: R25.2 R26.1
N13277238: Q3.1(BASE) R23.2 VR1.1
N13277284: Q2.1(G) R21.2 R22.1
N13277292: C15.2 D3.1 R18.1 U8.1
N13277372: Q2.3(D) R23.1
N13277482: R18.2 U8.4
N13277532: Q1.3(D) R22.2
N13277642: Q1.1(G) R19.2 R20.1
N13303706: R4.1 R5.1

Not connected (* = marked no-connect by the designer): J3 A9 A12 B1 B4 B6 B7 B9 B12 S2 S3 S4; Q5 2(S2) 3(S3) 6(D6) 7(D7) 8(D8); Q6 2(S2) 3(S3) 6(D6) 7(D7) 8(D8); Q7 2(S2) 3(S3) 6(D6) 7(D7) 8(D8); T1 2; T2 2 4; U1 3; U3 1 2 4 5 6 11; U4 3 12 13 14 16; U5 2 5 6 7 8 9 10 11 12 13 20 21 23; U8 6 7

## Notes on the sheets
sheet 1
- Input Protection, EMI Filter, and Rectifier Section
- AC Input
  90-264 VAC
sheet 2
- Ensure populate correct D1 part
- PFC Stage
- *
- *
- *
- *Do not populate
sheet 3
- PFC Bias Circuit
sheet 4
- Flyback Stage
- (VO)
sheet 5
- uCONTROLLER STAGE
- TYPE-C CONNECTOR
